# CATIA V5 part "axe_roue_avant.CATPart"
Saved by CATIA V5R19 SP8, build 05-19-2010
Part number: axe_roue_avant
Bounding box of the stored display mesh (mm): x 0 to 70, y -7.5 to 7.5, z -7.312 to 7.312
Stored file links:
  U:\Thinkmotion\Assemblage final\axe_roue_avant.CATPart
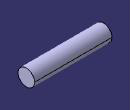
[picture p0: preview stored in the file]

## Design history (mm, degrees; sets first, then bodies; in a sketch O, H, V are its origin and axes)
Body1 (main body)
  Sketch1 on yz-plane, origin (0, 0, 0), H (0, 1, 0), V (0, 0, 1)
    circle A1 centre (0, 0) radius 7.5
    radius A1 = 7.5
  Pad1: profile Sketch1, direction (1, 0, 0), length 70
